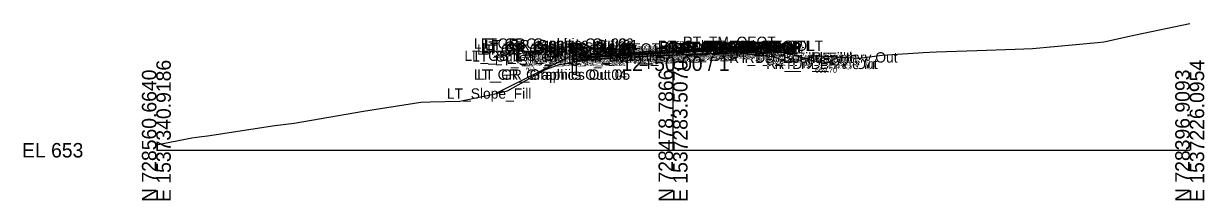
# Model space of a CAD drawing. Extents: x -26 to 1203, y -10 to 9522.
# Drawn here: x -25.7 to 202.8, y 2490.3 to 2524.5 of the extents above; entities that cross this region are included whole.
import ezdxf

# ---------------------------------------------------------------- set-up
doc = ezdxf.new("R2010")
doc.units = 0
for name, color, linetype in [('Default', 7, 'Continuous'), ('Exist CMT Pavement', 7, 'Continuous'), ('Exist Cross Section Cell', 7, 'Continuous'), ('Exist XS Center Line Elevation Label', 7, 'Continuous'), ('Exist XS Ground Line', 7, 'Continuous'), ('Old_Level_63', 7, 'Continuous'), ('Prop CMT Ditch DDE', 7, 'Continuous'), ('Prop CMT Guardrail Graphics', 7, 'Continuous'), ('Prop CMT Pvmt Course 1', 7, 'Continuous'), ('Prop CMT Pvmt Course 1 Wedge', 7, 'Continuous'), ('Prop CMT Pvmt Course 2 Wedge', 7, 'Continuous'), ('Prop CMT Pvmt Course 3', 7, 'Continuous'), ('Prop CMT Pvmt Course 3 Wedge', 7, 'Continuous'), ('Prop CMT Pvmt Surface', 7, 'Continuous'), ('Prop CMT Pvmt Surface Shoulder', 7, 'Continuous'), ('Prop CMT Pvmt Wedge Surface 1', 7, 'Continuous'), ('Prop CMT Pvmt Wedge Surface 2', 7, 'Continuous'), ('Prop CMT Pvmt Wedge Surface 3', 7, 'Continuous'), ('Prop CMT Shld Paved Course 1', 7, 'Continuous'), ('Prop CMT Shld Paved Course 2', 7, 'Continuous'), ('Prop CMT Shld Paved Course 3', 7, 'Continuous'), ('Prop CMT Slope Grass', 7, 'Continuous'), ('Prop CMT Subgrade Earthwork', 7, 'Continuous'), ('Prop Superelevation  Arrow CELL', 7, 'Continuous'), ('Prop XS Ditch Slope Text', 7, 'Continuous'), ('Prop XS Ditch Standard Text', 7, 'Continuous'), ('Prop XS EOT Tick Mark', 7, 'Continuous'), ('Prop XS SE Text', 7, 'Continuous'), ('Prop XS Side Slope Text', 7, 'Continuous')]:
    doc.layers.add(name, color=color, linetype=linetype)

msp = doc.modelspace()

# ---------------------------------------------------------------- linework, layer by layer
at = {"layer": 'Exist CMT Pavement'}
for points in [[(100, 2518.42), (101.22, 2518.46), (105.5, 2518.61), (109.78, 2518.77), (111, 2518.81)], [(100, 2518.42), (99.8, 2518.41), (99.2, 2518.39), (98.78, 2518.36), (98.59, 2518.36), (94.5, 2518.16), (90.22, 2517.96), (89, 2517.9)]]:
    msp.add_lwpolyline(points, dxfattribs=at)
at = {"layer": 'Exist Cross Section Cell'}
for p, q in [((100, 2500), (100, 2518.14)), ((0, 2500), (100, 2500)), ((100, 2500), (200, 2500))]:
    msp.add_line(p, q, dxfattribs=at)
at = {"layer": 'Exist XS Ground Line'}
msp.add_lwpolyline([(0, 2501.05), (6.86, 2502.38), (7.83, 2502.5), (8.29, 2502.58), (9.92, 2502.8), (22.95, 2504.8), (26.67, 2505.27), (40.08, 2507.54), (51.21, 2509.3), (52.99, 2509.39), (58.74, 2509.51), (65.26, 2510.87), (67.95, 2511.51), (75.29, 2515.59), (77.65, 2516.45), (80.8, 2517.19), (85.7, 2517.71), (86.32, 2517.77), (98.59, 2518.36), (99.2, 2518.39), (99.8, 2518.41), (100, 2518.42), (112.37, 2518.86), (113.01, 2518.79), (119.38, 2518.11), (122.18, 2517.11), (122.55, 2516.94), (126.64, 2518.01), (127.22, 2518.17), (127.64, 2518.27), (127.77, 2518.27), (128.25, 2518.27), (136.12, 2517.81), (140.5, 2518.38), (148.41, 2518.89), (149.61, 2518.94), (150.96, 2519.01), (158.77, 2519.29), (166.22, 2519.55), (169.59, 2519.7), (182.15, 2520.84), (183.35, 2521), (189.51, 2522.34), (200, 2524.49)], dxfattribs=at)
at = {"layer": 'Prop CMT Ditch DDE'}
for points in [[(125.7, 2517.77), (129.5, 2516.7)], [(126.21, 2517.9), (126.21, 2517.9)], [(129.5, 2516.7), (132.18, 2518.04)], [(131, 2516.7), (131, 2516.7)]]:
    msp.add_lwpolyline(points, dxfattribs=at)
at = {"layer": 'Prop CMT Guardrail Graphics'}
for points in [[(80.55, 2514.63), (80.55, 2520.63)], [(80.55, 2520.63), (81.89, 2520.63), (82.16, 2520.34)], [(82.16, 2519.75), (81.89, 2519.46), (81.22, 2519.46)], [(81.22, 2519.46), (81.22, 2514.63)], [(82.16, 2520.34), (81.89, 2520.04)], [(81.89, 2520.04), (82.16, 2519.75)], [(81.22, 2514.63), (80.55, 2514.63)]]:
    msp.add_lwpolyline(points, dxfattribs=at)
at = {"layer": 'Prop CMT Pvmt Course 1'}
for points in [[(100, 2519.33), (89, 2518.69)], [(89, 2518.44), (100, 2519.08)], [(89, 2518.69), (89, 2518.44), (89, 2518.44), (89, 2518.44)], [(100, 2519.33), (111, 2519.97)], [(111, 2519.72), (100, 2519.08)], [(100, 2519.08), (100, 2519.33)], [(100, 2519.08), (100, 2519.33)], [(111, 2519.97), (111, 2519.72), (111, 2519.72), (111, 2519.72)]]:
    msp.add_lwpolyline(points, dxfattribs=at)
at = {"layer": 'Prop CMT Pvmt Course 1 Wedge'}
for points in [[(89, 2518.44), (98.59, 2519), (99.2, 2519.03), (99.8, 2519.07), (100, 2519.08)], [(100, 2518.96), (99.8, 2518.94), (99.2, 2518.91), (98.59, 2518.87), (89, 2518.32)], [(89, 2518.32), (89, 2518.44)], [(100, 2519.08), (111, 2519.72)], [(111, 2519.6), (100, 2518.96)], [(100, 2519.08), (100, 2518.96)], [(100, 2518.96), (100, 2519.08)], [(111, 2519.72), (111, 2519.6)]]:
    msp.add_lwpolyline(points, dxfattribs=at)
at = {"layer": 'Prop CMT Pvmt Course 2 Wedge'}
for points in [[(89, 2518.44), (98.59, 2519), (99.2, 2519.03), (99.8, 2519.07), (100, 2519.08)], [(100, 2518.87), (99.8, 2518.86), (99.2, 2518.83), (98.59, 2518.79), (89, 2518.23)], [(89, 2518.23), (89, 2518.44)], [(100, 2519.08), (111, 2519.72)], [(111, 2519.51), (100, 2518.87)], [(100, 2519.08), (100, 2518.87)], [(100, 2518.87), (100, 2519.08)], [(111, 2519.72), (111, 2519.51)]]:
    msp.add_lwpolyline(points, dxfattribs=at)
at = {"layer": 'Prop CMT Pvmt Course 3'}
for points in [[(111, 2519.51), (111, 2519.51), (111, 2519.14), (111, 2519.14)], [(111, 2519.14), (111, 2519.51)], [(89, 2518.23), (89, 2518.23), (89, 2517.86), (89, 2517.86)], [(89, 2517.86), (89, 2518.23)]]:
    msp.add_lwpolyline(points, dxfattribs=at)
at = {"layer": 'Prop CMT Pvmt Course 3 Wedge'}
for points in [[(89, 2518.23), (98.59, 2518.79), (99.2, 2518.83), (99.8, 2518.86), (100, 2518.87)], [(100, 2518.87), (111, 2519.51)], [(100, 2518.87), (100, 2518.42)], [(100, 2518.42), (100, 2518.87)], [(111, 2518.81), (100, 2518.42)], [(111, 2519.51), (111, 2518.81)], [(100, 2518.42), (99.8, 2518.41), (99.2, 2518.39), (98.59, 2518.36), (89, 2517.9)], [(89, 2517.9), (89, 2518.23)]]:
    msp.add_lwpolyline(points, dxfattribs=at)
at = {"layer": 'Prop CMT Pvmt Surface'}
for points in [[(100, 2519.33), (89, 2518.69)], [(100, 2519.33), (111, 2519.97)]]:
    msp.add_lwpolyline(points, dxfattribs=at)
at = {"layer": 'Prop CMT Pvmt Surface Shoulder'}
for points in [[(89, 2518.69), (82.17, 2518.29)], [(111, 2519.97), (115, 2520.2)]]:
    msp.add_lwpolyline(points, dxfattribs=at)
at = {"layer": 'Prop CMT Pvmt Wedge Surface 1'}
for points in [[(100, 2519.08), (89, 2518.44)], [(89, 2518.44), (89, 2518.69)], [(89, 2518.69), (89, 2518.69)], [(100, 2519.08), (111, 2519.72)], [(111, 2519.72), (111, 2519.97)], [(111, 2519.97), (111, 2519.97)]]:
    msp.add_lwpolyline(points, dxfattribs=at)
at = {"layer": 'Prop CMT Pvmt Wedge Surface 2'}
for points in [[(100, 2519.08), (89, 2518.44)], [(89, 2518.44), (89, 2518.69)], [(89, 2518.44), (89, 2518.44)], [(100, 2519.08), (111, 2519.72)], [(111, 2519.72), (111, 2519.97)], [(111, 2519.72), (111, 2519.72)]]:
    msp.add_lwpolyline(points, dxfattribs=at)
at = {"layer": 'Prop CMT Pvmt Wedge Surface 3'}
for points in [[(100, 2518.87), (89, 2518.23)], [(89, 2518.23), (89, 2518.69)], [(100, 2518.87), (111, 2519.51)], [(111, 2519.51), (111, 2519.97)], [(111, 2519.51), (111, 2519.51)], [(89, 2518.23), (89, 2518.23)]]:
    msp.add_lwpolyline(points, dxfattribs=at)
at = {"layer": 'Prop CMT Shld Paved Course 1'}
for points in [[(89, 2518.69), (82.17, 2518.29), (81.9, 2518.03)], [(81.9, 2518.03), (89, 2518.44)], [(89, 2518.44), (89, 2518.69)], [(111, 2519.97), (115, 2520.2), (115.24, 2519.97)], [(115.24, 2519.97), (111, 2519.72)], [(111, 2519.72), (111, 2519.97)]]:
    msp.add_lwpolyline(points, dxfattribs=at)
at = {"layer": 'Prop CMT Shld Paved Course 2'}
for points in [[(89, 2518.44), (81.9, 2518.03), (81.68, 2517.81)], [(89, 2518.23), (89, 2518.44)], [(111, 2519.72), (115.24, 2519.97), (115.43, 2519.77)], [(115.43, 2519.77), (111, 2519.51)], [(111, 2519.51), (111, 2519.72)], [(81.68, 2517.81), (89, 2518.23)]]:
    msp.add_lwpolyline(points, dxfattribs=at)
at = {"layer": 'Prop CMT Shld Paved Course 3'}
for points in [[(111, 2519.51), (115.43, 2519.77)], [(111, 2519.14), (111, 2519.51)], [(115.79, 2519.42), (111, 2519.14)], [(115.43, 2519.77), (115.43, 2519.77)], [(115.43, 2519.77), (115.79, 2519.42)], [(81.28, 2517.41), (89, 2517.86)], [(81.68, 2517.81), (81.28, 2517.41)], [(89, 2518.23), (81.68, 2517.81)], [(81.68, 2517.81), (81.68, 2517.81)], [(89, 2517.86), (89, 2518.23)]]:
    msp.add_lwpolyline(points, dxfattribs=at)
at = {"layer": 'Prop CMT Slope Grass'}
for points in [[(115, 2520.2), (117, 2520.2)], [(117, 2520.2), (125.7, 2517.77)], [(80, 2518.12), (65.71, 2510.97)], [(82.16, 2518.29), (80, 2518.12)], [(82.17, 2518.29), (82.16, 2518.29)]]:
    msp.add_lwpolyline(points, dxfattribs=at)
at = {"layer": 'Prop CMT Subgrade Earthwork'}
for points in [[(111, 2519.14), (115.79, 2519.42)], [(111, 2519.14), (111, 2518.81)], [(111, 2519.14), (111, 2519.14)], [(115.79, 2519.42), (116.57, 2520.2)], [(81.28, 2517.41), (80.53, 2518.16)], [(89, 2517.86), (81.28, 2517.41)], [(89, 2517.86), (89, 2517.9)], [(89, 2517.86), (89, 2517.86)]]:
    msp.add_lwpolyline(points, dxfattribs=at)
at = {"layer": 'Prop Superelevation  Arrow CELL'}
msp.add_line((102.75, 2519.92), (96.76, 2519.56), dxfattribs=at)
msp.add_lwpolyline([(96.76, 2519.56), (98.23, 2520.15), (97.91, 2519.63)], close=True, dxfattribs=at)
at = {"layer": 'Prop XS EOT Tick Mark'}
for points in [[(111, 2519.97), (111, 2520.97)], [(89, 2518.69), (89, 2519.69)]]:
    msp.add_lwpolyline(points, dxfattribs=at)

# ---------------------------------------------------------------- texts
at = {"layer": 'Default'}
msp.add_text('-', height=0.0001, dxfattribs=at).set_placement((0, 2500))
msp.add_text('-', height=0.0001, dxfattribs=at).set_placement((0, 2500))
msp.add_text('-', height=0.0001, dxfattribs=at).set_placement((0, 2500))
at = {"layer": 'Exist Cross Section Cell'}
for s, p in [('L', (90, 2518.14)), ('12+50.00 / 1', (90, 2515.34)), ('EL 653', (-26, 2498.6))]:
    msp.add_text(s, height=2.8, dxfattribs=at).set_placement(p)
for s, p in [('E 1537340.9186', (2.8, 2490)), ('E 1537283.5070', (102.8, 2490)), ('E 1537226.0954', (202.8, 2490)), ('N 728560.6640', (0, 2490)), ('N 728478.7866', (100, 2490)), ('N 728396.9093', (200, 2490))]:
    msp.add_text(s, height=2.8, rotation=90, dxfattribs=at).set_placement(p)
at = {"layer": 'Exist XS Center Line Elevation Label'}
msp.add_text('671.42', height=0.75, dxfattribs=at).set_placement((98.61, 2517.34))
at = {"layer": 'Old_Level_63'}
for s, p in [('LT_GR_Graphics Out 03', (61.45, 2519.63)), ('LT_GR_Graphics Out 02', (62.79, 2519.63)), ('LT_GR_Graphics Out 09', (62.79, 2519.04)), ('LT_GR_Graphics Out 08', (63.06, 2518.75)), ('LT_GR_Graphics Out 01', (63.62, 2519.34)), ('LT_TM_OEOT', (79.94, 2518.69)), ('RT_Sub_Trench_Out_DLT', (97.09, 2519.2)), ('RT_PV1_OEEOP_Null', (97.41, 2518.97)), ('RT_PV1_OEEOP_W', (98.94, 2518.72)), ('RT_PV2_OEEOP', (100.26, 2518.72)), ('RT_PV2_OEOT', (101.13, 2518.72)), ('RT_PS3_Shelf_Out', (101.37, 2518.77)), ('RT_PV1_OEOT', (101.69, 2518.97)), ('RT_TM_OEOT', (101.9, 2519.97)), ('RT_PS2_OEOP', (105.43, 2518.97)), ('RT_PS3_OEOP', (105.62, 2518.77)), ('RT_PS1_OEOP', (105.76, 2519.2)), ('RT_GS_OS_CTL', (106.32, 2519.2)), ('LT_GS_OS_GR_Face_Graphics', (59.62, 2517.29)), ('LT_Sub_Trench_Out_DLT', (61.1, 2517.16)), ('LT_GR_Graphics Out 06', (62.07, 2518.46)), ('LT_GR_Graphics Out 07', (62.79, 2518.46)), ('LT_Sub_Trench_Out', (65.49, 2516.41)), ('LT_PS3_Shelf_Out', (67.67, 2516.81)), ('LT_GS_OS_CTL', (69.37, 2517.12)), ('LT_PS3_OEOP', (71.92, 2516.81)), ('LT_PS2_OEOP', (72.14, 2517.03)), ('LT_PS1_OEOP', (72.97, 2517.29)), ('LT_PV_Sub_Tie_Out', (73.95, 2516.9)), ('LT_PV1_OEEOP_Null', (75.46, 2517.69)), ('LT_PV_EG_TestPt3', (75.73, 2516.96)), ('LT_PV_OEEOP_EG', (76.54, 2516.9)), ('LT_PV1_OEEOP_W', (76.98, 2517.44)), ('LT_Sub_OEEOP', (78.21, 2516.86)), ('LT_PV2_OEEOP', (78.31, 2517.44)), ('LT_PV3_OEEOP', (78.31, 2517.23)), ('LT_Sub_OEOT', (79.08, 2516.86)), ('LT_PV2_OEOT', (79.17, 2517.44)), ('LT_PV3_OEOT', (79.17, 2517.23)), ('LT_PV1_OEOT', (79.74, 2517.69)), ('LT_PV_EG_TestPt2', (80.01, 2517.16)), ('LT_PV_EG_TestPt1', (84.86, 2517.36)), ('RT_PV_EG_TestPt1', (87.25, 2517.46)), ('RT_Seek SS Fill O', (89.44, 2518.33)), ('RT_PV_EG_TestPt2', (90.96, 2517.61)), ('PV_EPGL_EG', (91.24, 2517.42)), ('PV2_PGL_W', (92.02, 2518.08)), ('PV3_PGL_W', (92.02, 2517.87)), ('PV1_PGL_W', (92.58, 2518.08)), ('PV1_PGL', (94.47, 2518.33)), ('RT_PV_EG_TestPt3', (95.24, 2517.77)), ('RT_PV_Sub_Tie_Out', (95.9, 2517.81)), ('RT_PV_OEEOP_EG', (98.49, 2517.81)), ('RT_Sub_Trench_Out', (99.94, 2518.42)), ('RT_Sub_OEEOP', (100.17, 2518.14)), ('RT_PV3_OEEOP', (100.26, 2518.51)), ('RT_Sub_OEOT', (101.03, 2518.14)), ('RT_PV3_OEOT', (101.13, 2518.51)), ('RT_DD_Boundary In', (110.85, 2516.9)), ('RT_SS_Fill_Point', (113.84, 2516.9)), ('RT_DD_Boundary Out', (116.55, 2516.96)), ('RT_Slope_Fill', (116.68, 2516.9)), ('RT_DD_Base Out', (118.04, 2515.7)), ('RT_DD_Base In', (119.66, 2515.7)), ('LT_GR_Graphics Out 04', (61.45, 2513.63)), ('LT_GR_Graphics Out 05', (62.12, 2513.63)), ('LT_Slope_Fill', (56.23, 2509.97))]:
    msp.add_text(s, height=2, dxfattribs=at).set_placement(p)
at = {"layer": 'Prop XS Ditch Slope Text'}
for s, rotation, p in [('4:1', 345.9638, (125.24, 2516.68)), ('2:1', 26.5651, (131.2, 2516.09))]:
    msp.add_text(s, height=1, rotation=rotation, dxfattribs=at).set_placement(p)
at = {"layer": 'Prop XS Ditch Standard Text'}
msp.add_text('669.70', height=1, dxfattribs=at).set_placement((127.49, 2515.01))
at = {"layer": 'Prop XS SE Text'}
msp.add_text('0.058', height=1, rotation=3.3295, dxfattribs=at).set_placement((98.68, 2519.97))
at = {"layer": 'Prop XS Side Slope Text'}
for s, rotation, p in [('4:1', 345.9638, (121.02, 2519.97)), ('2:1', 26.5651, (71.81, 2514.86))]:
    msp.add_text(s, height=1, rotation=rotation, dxfattribs=at).set_placement(p)

doc.saveas('drawing.dxf')
